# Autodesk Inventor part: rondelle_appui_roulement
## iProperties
Created: 2011-01
Part Number: rondelle_appui_roulement
Document SubType Name: Modeling
Designer: eric
Density: 1 g/cm^3
Mass: 2.77992 g
Surface Area: 30.8165 cm^2
Volume: 2.77992 cm^3
Author: eric
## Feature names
1. Base1
